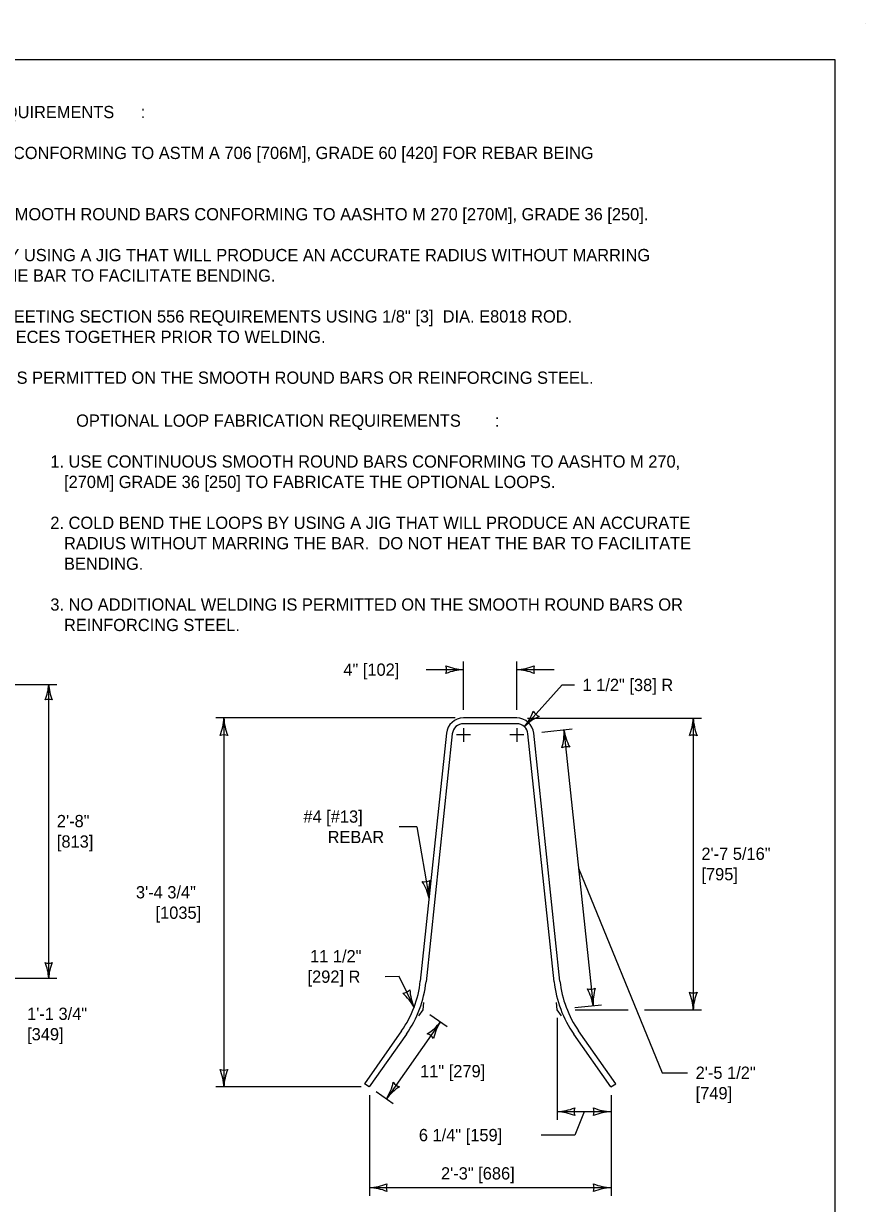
# Model space of a CAD drawing. Extents: x 49991.4 to 50021, y 49987.6 to 50011.4.
# Drawn here: x 50012.78 to 50016.9, y 49993.4 to 49999.18 of the extents above; entities that cross this region are included whole.
import ezdxf

# ---------------------------------------------------------------- set-up
doc = ezdxf.new("R2010")
doc.units = 0
for name, color, linetype in [('Level 1', 7, 'Continuous'), ('Level 2', 7, 'Continuous'), ('Level 3', 7, 'Continuous')]:
    doc.layers.add(name, color=color, linetype=linetype)

msp = doc.modelspace()

# ---------------------------------------------------------------- linework, layer by layer
at = {"layer": 'Level 1'}
for p, q in [((50016.9001, 49999.1756), (50016.9001, 49999.1756)), ((50015.1951, 49995.7775), (50014.9345, 49995.7775)), ((50015.1951, 49995.7492), (50014.9345, 49995.7492)), ((50014.8515, 49995.703), (50014.7231, 49994.4895)), ((50014.8797, 49995.7), (50014.7514, 49994.4865)), ((50015.3783, 49994.4865), (50015.2499, 49995.7)), ((50015.4065, 49994.4895), (50015.2782, 49995.703)), ((50014.6319, 49994.2464), (50014.4506, 49993.988)), ((50014.6552, 49994.2301), (50014.4739, 49993.9718)), ((50015.6558, 49993.9718), (50015.4744, 49994.2301)), ((50015.6791, 49993.988), (50015.4977, 49994.2464)), ((50014.4739, 49993.9718), (50014.4506, 49993.988)), ((50015.6558, 49993.9718), (50015.6791, 49993.988))]:
    msp.add_line(p, q, dxfattribs=at)
msp.add_lwpolyline([(49999.3835, 49998.9992), (50016.7501, 49998.9992), (50016.7501, 49987.7988), (49999.3835, 49987.7988)], close=True, dxfattribs=at)
for centre, major_axis, start_param, end_param in [((50014.9345, 49995.6943), (-0.0835, 0), 4.712389, 6.178105), ((50015.1951, 49995.6943), (0.0835, 0), 0.10508, 1.570796), ((50014.9345, 49995.6943), (-0.0551, 0), 4.712389, 6.178105), ((50015.1951, 49995.6943), (-0.0551, 0), 3.246673, 4.712389), ((50014.2057, 49994.5439), (0.5203, 0), 5.672459, 6.178105), ((50014.2057, 49994.5439), (0.5487, 0), 5.672459, 6.178105), ((50015.9239, 49994.5439), (-0.5487, 0), 0.10508, 0.610726), ((50015.9239, 49994.5439), (-0.5203, 0), 0.10508, 0.610726)]:
    msp.add_ellipse(centre, major_axis=major_axis, ratio=0.997211, start_param=start_param, end_param=end_param, dxfattribs=at)
at = {"layer": 'Level 3'}
for p, q in [((50014.7519, 49996.0141), (50014.9345, 49996.0141)), ((50014.9345, 49995.8175), (50014.9345, 49996.0541)), ((50015.1951, 49995.8175), (50015.1951, 49996.0541)), ((50015.1951, 49996.0141), (50015.3778, 49996.0141)), ((50011.7581, 49995.9422), (50012.9459, 49995.9422)), ((50012.9059, 49994.5042), (50012.9059, 49995.9422)), ((50015.2325, 49995.7346), (50015.4173, 49995.9393)), ((50015.4173, 49995.9393), (50015.4768, 49995.9393)), ((50014.8945, 49995.7775), (50013.7228, 49995.7775)), ((50013.7628, 49995.7775), (50013.7628, 49993.9718)), ((50015.2478, 49995.7766), (50016.0982, 49995.7765)), ((50016.0582, 49995.7765), (50016.0582, 49994.3497)), ((50014.9345, 49995.728), (50014.9345, 49995.6605)), ((50015.1951, 49995.728), (50015.1951, 49995.6605)), ((50015.4658, 49995.7228), (50015.318, 49995.7072)), ((50015.4261, 49995.7186), (50015.5689, 49994.3682)), ((50014.9682, 49995.6943), (50014.9007, 49995.6943)), ((50015.2289, 49995.6943), (50015.1614, 49995.6943)), ((50014.7068, 49995.2452), (50014.6194, 49995.2452)), ((50014.7068, 49995.2452), (50014.7661, 49994.8955)), ((50012.6107, 49994.5042), (50012.9459, 49994.5042)), ((50014.6192, 49994.5118), (50014.5522, 49994.5116)), ((50014.693, 49994.3622), (50014.6192, 49994.5118)), ((50014.7374, 49994.3497), (50014.7412, 49994.3855)), ((50015.3928, 49994.3497), (50015.3891, 49994.3855)), ((50014.7166, 49994.32), (50014.7374, 49994.3497)), ((50015.4137, 49994.32), (50015.3928, 49994.3497)), ((50015.6087, 49994.3724), (50015.4793, 49994.3588)), ((50015.4815, 49994.3497), (50015.7405, 49994.3497)), ((50015.8205, 49994.3497), (50016.0982, 49994.3497)), ((50014.8219, 49994.2907), (50014.5574, 49993.9139)), ((50014.7702, 49994.3268), (50014.8547, 49994.2678)), ((50015.3928, 49994.3097), (50015.3928, 49993.8108)), ((50014.4339, 49993.9718), (50013.7228, 49993.9718)), ((50014.4746, 49993.9318), (50014.4746, 49993.4391)), ((50014.5068, 49993.9491), (50014.5902, 49993.891)), ((50015.656, 49993.9318), (50015.656, 49993.4391)), ((50015.656, 49993.8508), (50015.3928, 49993.8508)), ((50015.4795, 49993.7365), (50015.3146, 49993.7365)), ((50015.656, 49993.4791), (50014.4746, 49993.4791))]:
    msp.add_line(p, q, dxfattribs=at)
for points in [[(50015.4975, 49995.0434), (50015.9062, 49994.0416), (50016.03, 49994.0416)], [(50015.5244, 49993.8508), (50015.4795, 49993.7365), (50015.4795, 49993.7365)]]:
    msp.add_lwpolyline(points, dxfattribs=at)
for centre, radius, start, end in [((50014.9448, 49996.264), 0.2501, 247.45601, 267.63952), ((50014.7902, 49996.0141), 0.0616, 342.13882, 17.86118), ((50014.9474, 49995.7523), 0.2621, 92.82731, 112.07716), ((50015.1822, 49996.2759), 0.2621, 272.82731, 292.07716), ((50015.1848, 49995.7642), 0.2501, 67.45601, 87.63952), ((50015.3394, 49996.0141), 0.0616, 162.13882, 197.86118), ((50012.6837, 49995.9513), 0.2223, 337.45601, 357.63952), ((50013.1386, 49995.9537), 0.233, 182.82731, 202.07716), ((50012.9059, 49995.814), 0.0548, 72.13882, 107.86118), ((50013.5129, 49995.7878), 0.2501, 337.45601, 357.63952), ((50014.0246, 49995.7905), 0.2621, 182.82731, 202.07716), ((50015.0295, 49995.9004), 0.2621, 320.75806, 340.00791), ((50015.4112, 49995.5595), 0.2501, 115.38676, 135.57026), ((50015.3292, 49995.8417), 0.0616, 210.06956, 245.79192), ((50015.8083, 49995.7869), 0.2501, 337.45601, 357.63952), ((50016.32, 49995.7895), 0.2621, 182.82731, 202.07716), ((50015.1765, 49995.7025), 0.2501, 343.49339, 3.6769), ((50015.685, 49995.759), 0.2621, 188.86469, 208.11454), ((50013.7628, 49995.6333), 0.0616, 72.13882, 107.86118), ((50016.0582, 49995.6323), 0.0616, 72.13882, 107.86118), ((50015.4412, 49995.5751), 0.0616, 78.1762, 113.89856), ((50014.7419, 49995.0377), 0.0616, 261.76479, 297.48715), ((50014.5101, 49994.839), 0.2621, 12.45328, 31.70313), ((50015.0142, 49994.9272), 0.2501, 167.08198, 187.26549), ((50012.9059, 49994.6324), 0.0548, 252.13882, 287.86118), ((50012.6732, 49994.4927), 0.233, 2.82731, 22.07716), ((50013.128, 49994.495), 0.2223, 157.45601, 177.63952), ((50014.6292, 49994.4915), 0.0616, 278.40359, 314.12595), ((50014.9217, 49994.4635), 0.2501, 183.72079, 203.90429), ((50015.5537, 49994.5116), 0.0616, 258.1762, 293.89856), ((50015.3099, 49994.3278), 0.2621, 8.86469, 28.11454), ((50015.8185, 49994.3842), 0.2501, 163.49339, 183.6769), ((50014.464, 49994.2347), 0.2621, 29.09209, 48.34194), ((50016.0582, 49994.4939), 0.0616, 252.13882, 287.86118), ((50015.7964, 49994.3367), 0.2621, 2.82731, 22.07716), ((50016.3081, 49994.3394), 0.2501, 157.45601, 177.63952), ((50014.6233, 49994.4427), 0.2501, 302.38878, 322.57229), ((50015.0436, 49994.1508), 0.2621, 147.76008, 167.00993), ((50014.739, 49994.1726), 0.0616, 37.07159, 72.79395), ((50013.7628, 49994.116), 0.0616, 252.13882, 287.86118), ((50013.501, 49993.9589), 0.2621, 2.82731, 22.07716), ((50014.0127, 49993.9615), 0.2501, 157.45601, 177.63952), ((50014.3357, 49994.0537), 0.2621, 327.76008, 347.00993), ((50014.6403, 49994.0319), 0.0616, 217.07159, 252.79395), ((50014.756, 49993.7619), 0.2501, 122.38878, 142.57229), ((50015.3799, 49994.1126), 0.2621, 272.82731, 292.07716), ((50015.5371, 49993.8508), 0.0616, 162.13882, 197.86118), ((50015.6663, 49994.1007), 0.2501, 247.45601, 267.63952), ((50015.5117, 49993.8508), 0.0616, 342.13882, 17.86118), ((50015.3825, 49993.6009), 0.2501, 67.45601, 87.63952), ((50015.6689, 49993.589), 0.2621, 92.82731, 112.07716), ((50014.4617, 49993.7409), 0.2621, 272.82731, 292.07716), ((50014.4643, 49993.2292), 0.2501, 67.45601, 87.63952), ((50014.6188, 49993.4791), 0.0616, 162.13882, 197.86118), ((50015.6663, 49993.729), 0.2501, 247.45601, 267.63952), ((50015.5117, 49993.4791), 0.0616, 342.13882, 17.86118), ((50015.6689, 49993.2173), 0.2621, 92.82731, 112.07716)]:
    msp.add_arc(centre, radius, start, end, dxfattribs=at)

# ---------------------------------------------------------------- texts
at = {"layer": 'Level 2'}
for s, p in [('LOOP FABRICATION REQUIREMENTS', (50011.7732, 49998.7128)), (':', (50013.356, 49998.7128)), ('1. USE REINFORCING STEEL CONFORMING TO ASTM A 706 [706M], GRADE 60 [420] FOR REBAR BEING ', (50011.5943, 49998.5128)), ('2. LOOP ENDS CONSIST OF SMOOTH ROUND BARS CONFORMING TO AASHTO M 270 [270M], GRADE 36 [250].', (50011.5943, 49998.2128)), ('3. COLD BEND THE LOOPS BY USING A JIG THAT WILL PRODUCE AN ACCURATE RADIUS WITHOUT MARRING', (50011.5943, 49998.0128)), ('   THE BAR.  DO NOT HEAT THE BAR TO FACILITATE BENDING.', (50011.5943, 49997.9128)), ('4. WELD REBAR TO LOOPS MEETING SECTION 556 REQUIREMENTS USING 1/8" [3]  DIA. E8018 ROD.', (50011.5943, 49997.7128)), ('   DO NOT TACK WELD THE PIECES TOGETHER PRIOR TO WELDING.', (50011.5943, 49997.6128)), ('5. NO ADDITIONAL WELDING IS PERMITTED ON THE SMOOTH ROUND BARS OR REINFORCING STEEL.', (50011.5943, 49997.4128)), ('OPTIONAL LOOP FABRICATION REQUIREMENTS', (50013.0401, 49997.2028)), (':', (50015.0884, 49997.2028)), ('1. USE CONTINUOUS SMOOTH ROUND BARS CONFORMING TO AASHTO M 270, ', (50012.9139, 49997.0028)), ('   [270M] GRADE 36 [250] TO FABRICATE THE OPTIONAL LOOPS.   ', (50012.9139, 49996.9028)), ('2. COLD BEND THE LOOPS BY USING A JIG THAT WILL PRODUCE AN ACCURATE ', (50012.9139, 49996.7028)), ('   RADIUS WITHOUT MARRING THE BAR.  DO NOT HEAT THE BAR TO FACILITATE ', (50012.9139, 49996.6028)), ('   BENDING.', (50012.9139, 49996.5028)), ('3. NO ADDITIONAL WELDING IS PERMITTED ON THE SMOOTH ROUND BARS OR ', (50012.9139, 49996.3028)), ('   REINFORCING STEEL.', (50012.9139, 49996.2028)), ('4" [102]', (50014.3469, 49995.9841)), ('1 1/2" [38] R', (50015.5168, 49995.9093)), ('#4 [#13]', (50014.1517, 49995.2652)), ('2\'-8"', (50012.9459, 49995.243)), ('[813]', (50012.9459, 49995.143)), (' REBAR', (50014.2478, 49995.1652)), ('2\'-7 5/16"', (50016.0982, 49995.0831)), ('[795]', (50016.0982, 49994.9831)), ('3\'-4 3/4"', (50013.3324, 49994.8947)), ('[1035]', (50013.4285, 49994.7947)), ('11 1/2"', (50014.1842, 49994.5816)), ('[292] R', (50014.1718, 49994.4816)), ('1\'-1 3/4"', (50012.8004, 49994.3001)), ('[349]', (50012.8004, 49994.2001)), ('11" [279]', (50014.7224, 49994.0193)), ('2\'-5 1/2"', (50016.07, 49994.0116)), ('[749]', (50016.07, 49993.9116)), ('6 1/4" [159]', (50014.7162, 49993.7065)), ('2\'-3" [686]', (50014.8245, 49993.5191))]:
    msp.add_text(s, height=0.06, dxfattribs=at).set_placement(p)

doc.saveas('drawing.dxf')
